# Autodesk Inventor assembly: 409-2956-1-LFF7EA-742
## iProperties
Created: 2010-09
Part Number: 409-2956-1-LFF7EA-742
Document SubType Name: Weldment
Designer: S. Boerckel
Weld Material: Welded Steel Mild
Mass: 38238.7 g
Surface Area: 12509.7 cm^2
Volume: 4861.71 cm^3
Density: 7.86528 g/cm^3
Description: DISCHARGE SPOOL
Material: WELDMENT
SMR: =<MATERIAL>
Author: S. Boerckel
Revision Number: A
